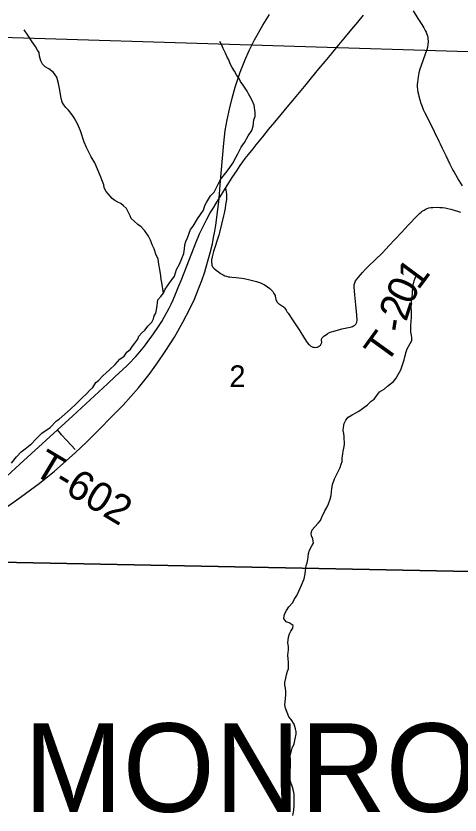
# Model space of a CAD drawing. Extents: x 0 to 34, y 0 to 22.
# Drawn here: x 2.749 to 3.604, y 15.391 to 16.93 of the extents above; entities that cross this region are included whole.
import ezdxf

# ---------------------------------------------------------------- set-up
doc = ezdxf.new("R2010")
doc.units = 0
for name, color, linetype in [('GM_X_Corporation', 7, 'Continuous'), ('GM_X_County_Road', 7, 'Continuous'), ('GM_X_County_Road_Text', 7, 'Continuous'), ('GM_X_Interchange_Ramps', 7, 'Continuous'), ('GM_X_Interstate_Route', 7, 'Continuous'), ('GM_X_Minor_Lake', 7, 'Continuous'), ('GM_X_Section', 7, 'Continuous'), ('GM_X_Section_Text', 7, 'Continuous'), ('GM_X_Township_Road_Text', 7, 'Continuous')]:
    doc.layers.add(name, color=color, linetype=linetype)

msp = doc.modelspace()

# ---------------------------------------------------------------- linework, layer by layer
at = {"layer": 'GM_X_Corporation'}
for points in [[(3.5132, 16.9403), (3.5227, 16.9257), (3.53, 16.9143), (3.5338, 16.9078), (3.5367, 16.9025), (3.5384, 16.899), (3.5397, 16.8955), (3.5407, 16.8923), (3.5414, 16.8892), (3.5419, 16.8861), (3.5422, 16.8827), (3.5418, 16.8745), (3.5413, 16.8716), (3.5402, 16.8674), (3.5392, 16.8641), (3.5336, 16.8481), (3.5288, 16.8348), (3.5265, 16.8279), (3.5246, 16.8212), (3.5228, 16.8132), (3.5221, 16.8078), (3.5216, 16.8032), (3.5213, 16.7984), (3.5214, 16.7937), (3.5218, 16.789), (3.5225, 16.7838), (3.5234, 16.7794), (3.5241, 16.7759), (3.526, 16.7688), (3.5281, 16.7624), (3.5306, 16.7558), (3.5329, 16.7504), (3.5359, 16.7441), (3.5452, 16.7253), (3.563, 16.6893)], [(3.563, 16.6893), (3.5656, 16.6839), (3.5693, 16.6758), (3.576, 16.6615), (3.5842, 16.6451), (3.5901, 16.6335), (3.5923, 16.6293), (3.5947, 16.6248), (3.5979, 16.6195), (3.6014, 16.6136), (3.6079, 16.6031)]]:
    msp.add_lwpolyline(points, dxfattribs=at)
at = {"layer": 'GM_X_County_Road'}
msp.add_lwpolyline([(2.6967, 15.9609), (2.7505, 15.9985), (2.7932, 16.0302), (2.8227, 16.0537), (2.8454, 16.0733), (2.8633, 16.0897), (2.8843, 16.1094), (2.9081, 16.133), (2.9333, 16.1587), (2.9549, 16.181), (2.9845, 16.2139), (3.0048, 16.2398), (3.0212, 16.2624), (3.0362, 16.2843), (3.0538, 16.312), (3.07, 16.3409), (3.0832, 16.3661), (3.0921, 16.3849), (3.1002, 16.4047), (3.1064, 16.4208), (3.1125, 16.4379), (3.1177, 16.4563), (3.1226, 16.4744), (3.1269, 16.4918), (3.1292, 16.5035), (3.1315, 16.5159), (3.1333, 16.5276), (3.1375, 16.5575), (3.139, 16.5724), (3.1402, 16.5872), (3.1419, 16.6052), (3.1436, 16.6274), (3.149, 16.6853), (3.1517, 16.7096), (3.1553, 16.7301), (3.1598, 16.7511), (3.1647, 16.7723), (3.1709, 16.7936), (3.1766, 16.8104), (3.1806, 16.8221), (3.1896, 16.8449), (3.1979, 16.8637), (3.2079, 16.8845), (3.2238, 16.9128), (3.2367, 16.9333)], dxfattribs=at)
at = {"layer": 'GM_X_Interchange_Ramps'}
msp.add_lwpolyline([(2.7224, 16.0363), (2.7563, 16.0669), (2.8287, 16.133), (2.8581, 16.1604), (2.925, 16.222), (2.939, 16.2351), (2.9618, 16.2564), (2.9659, 16.2605), (2.9796, 16.2748), (2.9841, 16.2797), (2.9904, 16.2873), (2.9966, 16.2952), (3.0027, 16.3032), (3.009, 16.3116), (3.015, 16.32), (3.0206, 16.3284), (3.0292, 16.3422), (3.034, 16.3503), (3.0399, 16.3608), (3.0434, 16.3675), (3.0472, 16.3755), (3.0511, 16.384), (3.0557, 16.3946), (3.0625, 16.4104), (3.0667, 16.421), (3.0826, 16.4623), (3.0947, 16.4936), (3.1023, 16.511), (3.107, 16.5214), (3.1161, 16.5389), (3.1228, 16.551), (3.1287, 16.5609), (3.1337, 16.5689), (3.1523, 16.5985), (3.1665, 16.6215), (3.1737, 16.6322), (3.1805, 16.6424), (3.1854, 16.6496), (3.1898, 16.6557), (3.1962, 16.6639), (3.2051, 16.6745), (3.2112, 16.682), (3.2239, 16.6979), (3.2351, 16.7116), (3.2471, 16.7259), (3.2594, 16.7407), (3.2709, 16.7545), (3.282, 16.7679), (3.2946, 16.7829), (3.3071, 16.7982), (3.3179, 16.8114), (3.3319, 16.8284), (3.3441, 16.8426), (3.3565, 16.858), (3.3705, 16.8751), (3.3831, 16.8901), (3.3955, 16.905), (3.4069, 16.9186), (3.4179, 16.9322)], dxfattribs=at)
at = {"layer": 'GM_X_Interstate_Route'}
for points in [[(3.1523, 16.5985), (3.1532, 16.5919), (3.1537, 16.5867), (3.1539, 16.5819), (3.1537, 16.5779), (3.1532, 16.5731), (3.1523, 16.5665), (3.1514, 16.5604), (3.1495, 16.5504), (3.1483, 16.5452), (3.1405, 16.5132), (3.1391, 16.508), (3.1289, 16.4765), (3.1261, 16.4662), (3.1252, 16.4608), (3.1248, 16.4576), (3.1255, 16.4503), (3.1273, 16.4471), (3.1297, 16.4446)], [(3.1297, 16.4446), (3.1341, 16.441), (3.1385, 16.4375), (3.1415, 16.4353), (3.1439, 16.4337), (3.1474, 16.4318), (3.1509, 16.4301), (3.1537, 16.429), (3.1573, 16.4283), (3.1605, 16.4278), (3.1645, 16.4275), (3.1721, 16.4267), (3.1836, 16.4253), (3.1877, 16.4245), (3.1989, 16.4223), (3.2115, 16.419), (3.214, 16.4182), (3.2196, 16.4162), (3.2231, 16.4147), (3.227, 16.4127), (3.2301, 16.4108), (3.2329, 16.409), (3.2376, 16.4052), (3.2398, 16.4032), (3.2431, 16.3998), (3.244, 16.3987), (3.2454, 16.3962), (3.2466, 16.3939), (3.2474, 16.3918), (3.2478, 16.3906), (3.2491, 16.3841), (3.2495, 16.3826), (3.2507, 16.3804), (3.2514, 16.3795), (3.2549, 16.3762), (3.2558, 16.3755), (3.262, 16.3717), (3.263, 16.3711), (3.2654, 16.369), (3.2663, 16.3679), (3.2687, 16.3641), (3.2711, 16.3601), (3.2725, 16.3578), (3.2813, 16.3452), (3.2838, 16.3415), (3.2949, 16.324), (3.3021, 16.3125), (3.3075, 16.304), (3.3093, 16.3015), (3.3118, 16.2986), (3.3135, 16.2968), (3.3163, 16.2947), (3.3176, 16.2939), (3.3205, 16.2926), (3.322, 16.2922), (3.3234, 16.292), (3.3274, 16.2923), (3.3289, 16.2928), (3.3316, 16.2941), (3.3328, 16.2948), (3.3347, 16.2965), (3.3357, 16.2977), (3.3369, 16.3002), (3.3374, 16.3013), (3.3374, 16.3023), (3.337, 16.3055), (3.3369, 16.3069), (3.337, 16.3079), (3.3377, 16.3094), (3.3384, 16.3104), (3.3417, 16.3136), (3.3432, 16.3149), (3.3484, 16.3185), (3.3498, 16.3194), (3.3537, 16.3213), (3.3561, 16.3222), (3.3606, 16.3236), (3.3723, 16.3267), (3.3758, 16.3276), (3.3923, 16.331), (3.3949, 16.3317), (3.3968, 16.3326), (3.3988, 16.3337), (3.4012, 16.335), (3.4028, 16.3366), (3.4038, 16.3379), (3.4047, 16.3407), (3.4056, 16.3448), (3.4051, 16.3544), (3.4031, 16.3741), (3.4012, 16.3932), (3.3999, 16.4082), (3.4001, 16.4128), (3.4012, 16.4167), (3.4026, 16.4203), (3.4122, 16.4321), (3.4158, 16.4364), (3.4217, 16.4426), (3.4275, 16.4483), (3.4407, 16.4611), (3.4536, 16.4737), (3.4611, 16.4814), (3.4675, 16.4882), (3.4782, 16.4998), (3.4913, 16.5139), (3.4975, 16.5206), (3.5041, 16.5276), (3.5213, 16.5458), (3.5255, 16.5501), (3.5285, 16.5528), (3.5305, 16.5543), (3.5344, 16.5567), (3.5387, 16.5588), (3.5421, 16.5602), (3.5438, 16.5606), (3.5476, 16.5613), (3.5516, 16.5616), (3.5595, 16.5619), (3.5647, 16.5617), (3.5702, 16.5613), (3.5749, 16.5607), (3.5801, 16.5595), (3.5858, 16.5581), (3.5989, 16.5544), (3.6044, 16.5527)], [(2.8629, 16.0956), (2.855, 16.1039), (2.8461, 16.1133), (2.8365, 16.1237), (2.8347, 16.1257), (2.8287, 16.133)]]:
    msp.add_lwpolyline(points, dxfattribs=at)
at = {"layer": 'GM_X_Minor_Lake'}
for points in [[(3.703, 16.8594), (3.6897, 15.9465), (3.688, 15.8589), (2.684, 15.8792), (2.6993, 16.8906)], [(2.684, 15.8792), (3.688, 15.8589), (3.6743, 14.926), (3.6733, 14.8581), (2.6707, 14.8651)]]:
    msp.add_lwpolyline(points, close=True, dxfattribs=at)
at = {"layer": 'GM_X_Township_Road_Text'}
for points in [[(3.0325, 16.3964), (3.0296, 16.4173), (3.0284, 16.4226), (3.0275, 16.4298), (3.0255, 16.442), (3.0234, 16.4522), (3.0221, 16.4617), (3.0182, 16.4716), (3.0147, 16.4822), (3.0115, 16.4886), (3.0076, 16.4984), (3.0041, 16.5064), (2.9967, 16.5169), (2.9898, 16.524), (2.9833, 16.5285), (2.9764, 16.5349), (2.9706, 16.5401), (2.9687, 16.5454), (2.9652, 16.5522), (2.9617, 16.5594), (2.9559, 16.565), (2.9505, 16.5695), (2.9448, 16.5721), (2.9387, 16.575), (2.9337, 16.5787), (2.9268, 16.587), (2.9222, 16.5923), (2.9187, 16.5994), (2.9175, 16.6051), (2.9151, 16.6116), (2.9108, 16.6233), (2.9006, 16.6475), (2.8936, 16.6592), (2.8885, 16.6694), (2.8846, 16.677), (2.8799, 16.6872), (2.8728, 16.7091), (2.8673, 16.7228), (2.8607, 16.7345), (2.8568, 16.7401), (2.8499, 16.7488), (2.8449, 16.754), (2.8406, 16.7593), (2.8375, 16.7642), (2.8347, 16.7756), (2.833, 16.7873), (2.8302, 16.8002), (2.827, 16.8127), (2.8212, 16.8214), (2.8116, 16.8285), (2.8051, 16.8322), (2.7997, 16.8378), (2.7962, 16.8442), (2.7938, 16.853), (2.793, 16.8598), (2.7903, 16.8647), (2.7864, 16.8715), (2.7798, 16.8805), (2.7717, 16.8934), (2.7647, 16.9039)], [(2.9399, 16.2591), (2.9485, 16.2695), (2.9571, 16.2753), (2.9623, 16.283), (2.9694, 16.2889), (2.9731, 16.2942), (2.9772, 16.3), (2.9831, 16.3081), (2.9853, 16.3135), (2.9905, 16.3193), (2.9965, 16.3251), (3.0032, 16.3335), (3.0103, 16.3409), (3.0132, 16.3474), (3.015, 16.3527), (3.018, 16.3581), (3.0194, 16.3646), (3.0204, 16.3726), (3.0211, 16.3776), (3.0218, 16.3837), (3.0274, 16.3899), (3.0326, 16.3964), (3.0362, 16.4041), (3.0448, 16.4172), (3.0537, 16.4291), (3.058, 16.4421), (3.0632, 16.4525), (3.0683, 16.4632), (3.0716, 16.4731), (3.073, 16.4819), (3.074, 16.4899), (3.0758, 16.496), (3.0791, 16.5033), (3.0849, 16.519), (3.0897, 16.5259), (3.0983, 16.5398), (3.1038, 16.5479), (3.1097, 16.5567), (3.1123, 16.5651), (3.1152, 16.5709), (3.1234, 16.5839), (3.1301, 16.5909), (3.1327, 16.5959), (3.1363, 16.6024), (3.1422, 16.6154), (3.1478, 16.6216), (3.1552, 16.6313), (3.1604, 16.6386), (3.1664, 16.647), (3.1719, 16.6578), (3.1756, 16.6647), (3.1822, 16.6777), (3.1885, 16.6866), (3.1959, 16.6996), (3.2026, 16.7096), (3.2051, 16.7184), (3.2068, 16.7303), (3.209, 16.7368), (3.2089, 16.7444), (3.2072, 16.7584), (3.204, 16.7664), (3.1997, 16.7747), (3.1966, 16.7804), (3.1935, 16.7856), (3.19, 16.7913), (3.1858, 16.7969), (3.1811, 16.8045), (3.1784, 16.8101), (3.1741, 16.8158), (3.1691, 16.8241), (3.1648, 16.8313), (3.1613, 16.8384), (3.1582, 16.846), (3.1555, 16.8513), (3.1519, 16.8588), (3.1473, 16.8675), (3.1449, 16.8743), (3.1414, 16.8815)], [(3.5099, 16.3809), (3.5113, 16.3893), (3.5119, 16.395), (3.5122, 16.4003), (3.5125, 16.4068), (3.5132, 16.4122), (3.5154, 16.4202), (3.5175, 16.4255), (3.5187, 16.4287)], [(3.2722, 15.699), (3.2729, 15.7043), (3.2735, 15.7093), (3.2734, 15.7161), (3.2722, 15.7233), (3.2732, 15.734), (3.2754, 15.7401), (3.2779, 15.7455), (3.2816, 15.7513), (3.2823, 15.7562), (3.2747, 15.7614), (3.2686, 15.7632), (3.2647, 15.77), (3.2657, 15.7784), (3.2698, 15.7853), (3.2738, 15.7926), (3.2817, 15.8007), (3.2846, 15.8065), (3.2891, 15.8142), (3.2935, 15.8226), (3.2982, 15.8341), (3.3034, 15.846), (3.3055, 15.8559), (3.3062, 15.8616), (3.3068, 15.8666), (3.3075, 15.8719), (3.309, 15.8769), (3.3104, 15.8834), (3.3114, 15.8887), (3.3121, 15.8952), (3.3135, 15.9013), (3.3183, 15.9098), (3.3213, 15.9152), (3.32, 15.9235), (3.3177, 15.9292), (3.3172, 15.9341), (3.319, 15.9406), (3.3242, 15.9464), (3.3302, 15.9537), (3.335, 15.9588), (3.3376, 15.9653), (3.3431, 15.9772), (3.3475, 15.9837), (3.3501, 15.9906), (3.3534, 15.9994), (3.3555, 16.007), (3.3562, 16.0147), (3.3569, 16.0196), (3.3579, 16.028), (3.3619, 16.0391), (3.3656, 16.0468), (3.3696, 16.0541), (3.3729, 16.061), (3.3747, 16.0671), (3.3765, 16.0724), (3.3768, 16.0785), (3.3778, 16.0869), (3.3789, 16.0923), (3.38, 16.098), (3.381, 16.1052), (3.3813, 16.1102), (3.3808, 16.1151), (3.3808, 16.1205), (3.3799, 16.1262), (3.3787, 16.1322), (3.3794, 16.1387), (3.3804, 16.1452), (3.3837, 16.1517), (3.3885, 16.1579), (3.3957, 16.1622), (3.4032, 16.1661), (3.4088, 16.1692), (3.4159, 16.1743), (3.4253, 16.1817), (3.4328, 16.1883), (3.4384, 16.1925), (3.4488, 16.2064), (3.4578, 16.2119), (3.4638, 16.2173), (3.4758, 16.2262), (3.481, 16.2331), (3.4843, 16.2397), (3.4898, 16.2489), (3.4924, 16.2565), (3.496, 16.268), (3.4974, 16.2741), (3.4999, 16.2837), (3.5021, 16.2894), (3.5076, 16.2994), (3.511, 16.3055), (3.5109, 16.3105), (3.5104, 16.3154), (3.5092, 16.3211), (3.5087, 16.3287), (3.5087, 16.3341), (3.5093, 16.3421), (3.5099, 16.3512), (3.5102, 16.3573), (3.5101, 16.3626), (3.5097, 16.3687), (3.5099, 16.3809)], [(2.7397, 16.0691), (2.7494, 16.0811), (2.7587, 16.0907), (2.7662, 16.0969), (2.7726, 16.1016), (2.7789, 16.107), (2.786, 16.1144), (2.7983, 16.1267), (2.8145, 16.138), (2.8264, 16.1504), (2.832, 16.1539), (2.8429, 16.1636), (2.8537, 16.1729), (2.8645, 16.1833), (2.8757, 16.1945), (2.8851, 16.2031), (2.8899, 16.2092), (2.8966, 16.2147), (2.9022, 16.2243), (2.9074, 16.2285), (2.916, 16.2374), (2.9287, 16.2486), (2.9399, 16.2591)], [(3.282, 15.3901), (3.2837, 15.4004), (3.2844, 15.4103), (3.2846, 15.4198), (3.2845, 15.4251), (3.284, 15.4316), (3.2828, 15.438), (3.2808, 15.4452), (3.2768, 15.4577), (3.2745, 15.4626), (3.2748, 15.4695), (3.2769, 15.4768), (3.2772, 15.484), (3.277, 15.4996), (3.2769, 15.5045), (3.2783, 15.5126), (3.2805, 15.5202), (3.2841, 15.5283), (3.2863, 15.5378), (3.288, 15.5473), (3.2883, 15.5523), (3.2871, 15.5576), (3.284, 15.5663), (3.2782, 15.5754), (3.2739, 15.5802), (3.2711, 15.5886), (3.2676, 15.5969), (3.2664, 15.6037), (3.2674, 15.6148), (3.2684, 15.6232), (3.2683, 15.6285), (3.2678, 15.6357), (3.2666, 15.6414), (3.2661, 15.6464), (3.2683, 15.6551), (3.2697, 15.6612), (3.2715, 15.6681), (3.2733, 15.6731), (3.2736, 15.6781), (3.2735, 15.6857), (3.2727, 15.6921), (3.2722, 15.699)]]:
    msp.add_lwpolyline(points, dxfattribs=at)

# ---------------------------------------------------------------- texts
at = {"layer": 'GM_X_County_Road_Text'}
msp.add_text('2', height=0.0419, rotation=0, dxfattribs=at).set_placement((3.1595, 16.2156))
at = {"layer": 'GM_X_Section'}
for s, height, rotation, p in [('1', 0.0568, 53.4351, (3.5232, 16.401)), ('0', 0.0568, 65.6069, (3.5104, 16.3719)), ('2', 0.0568, 72.067, (3.5002, 16.3402)), ('-', 0.0568, 81.1849, (3.4972, 16.3194)), ('T', 0.0568, 54.0533, (3.4612, 16.2581)), ('T-602', 0.05682, 329.0364, (2.7793, 16.0494))]:
    msp.add_text(s, height=height, rotation=rotation, dxfattribs=at).set_placement(p)
at = {"layer": 'GM_X_Section_Text'}
msp.add_text('MONROE', height=0.17045, rotation=0, dxfattribs=at).set_placement((2.7643, 15.3974))

doc.saveas('drawing.dxf')
